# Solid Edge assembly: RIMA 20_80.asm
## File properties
Title: Zylinder
Author: ahadarics
Template: iso metric assembly.asm
Last saved by: ahadarics
Revision: 5
Application: Solid Edge
Username: ahadarics
Dokumentum tartalom típus: 1
Document Number: RIMA 20/80
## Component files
Profilrohr.par
Kolbenstange.par
Kit_1.par
Kit_2.par
Mutter_1.par
Mutter_2.par
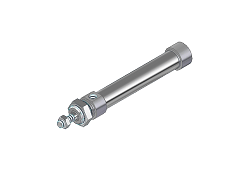
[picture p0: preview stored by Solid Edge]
